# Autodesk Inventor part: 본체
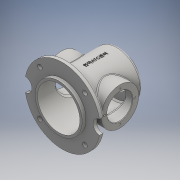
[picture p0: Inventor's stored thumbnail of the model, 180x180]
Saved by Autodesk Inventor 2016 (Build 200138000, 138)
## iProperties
Created: 2018-04
Part Number: 본체
Material: 일반
Document SubType Name: Modeling
Designer: 605-06
Density: 1 g/cm^3
Appearance: 기본값
Author: 605-06
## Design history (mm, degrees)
sketch "스케치1"
  geometry: C1 r 80 at (0, 0); 1 further point
  constraints: 1 centre point, 1 coincident
  dimensions: "d0" = 160 diameter of C1
extrude "돌출1" new body sketch "스케치1" distance "d1" = 10; taper "d2" = 0 deg
sketch "스케치2"
  geometry: C1 r 50 at (0, 0); 1 further point
  constraints: 1 centre point, 1 coincident
  dimensions: "d3" = 100 diameter of C1
extrude "돌출2" join sketch "스케치2" distance "d4" = 110; taper "d6" = 0 deg; dims "d5" = 18, "d7" = 0
sketch "스케치3"
  geometry: C1 r 40 at (0, 0); 1 further point
  constraints: 1 centre point, 1 coincident
  dimensions: "d8" = 80 diameter of C1
extrude "돌출3" join sketch "스케치3" distance "d9" = 5; taper "d10" = 0 deg
sketch "스케치4"
  geometry: C1 r 15 at (-80, 0); C2 r 15 at (80, 0); A1 r 80 centre (0, 0) between (-80, 0) and (80, 0) reference; 1 further point
  constraints: 2 centre point, 2 horizontal alignment, 2 point on circle
  dimensions: "d11" = 30 diameter of C1; "d12" = 30 diameter of C2
extrude "돌출4" cut sketch "스케치4" stored distance "d13" = 0; taper "d14" = 0 deg
sketch "스케치5"
  geometry: C1 r 40 at (60, 0); 1 further point
  constraints: 1 centre point, 1 horizontal alignment
  dimensions: "d15" = 80 diameter of C1; "d16" = 60 distance of C1.centre point (0, 0)
extrude "돌출5" join sketch "스케치5" stored distance "d17" = 124; taper "d18" = 0 deg
sketch "스케치6"
  geometry: C1 r 45 at (0, 0); 1 further point
  constraints: 1 centre point, 1 coincident
  dimensions: "d19" = 90 diameter of C1
extrude "돌출6" cut sketch "스케치6" distance "d20" = 120; taper "d21" = 0 deg
sketch "스케치7"
  geometry: C1 r 27 at (0, 0); 1 further point
  constraints: 1 centre point, 1 coincident
  dimensions: "d22" = 54 diameter of C1
extrude "돌출7" cut sketch "스케치7" stored distance "d23" = 120; taper "d24" = 0 deg
sketch "스케치8"
  geometry: C1 r 27 at (0, 0); C2 r 40 at (0, 0) reference; 1 further point
  constraints: 1 centre point, 1 concentric
  dimensions: "d25" = 54 diameter of C1
extrude "돌출8" cut sketch "스케치8" stored distance "d26" = 0; taper "d27" = 0 deg
sketch "스케치9"
  geometry: L1 (0, 67.5)-(0, -67.5); L2 (-47.73, 47.73)-(47.73, -47.73); L3 (-67.5, 0)-(67.5, 0); L4 (-47.73, -47.73)-(47.73, 47.73); L5 (0, -67.5)-(0, 67.5); L6 (47.73, -47.73)-(-47.73, 47.73); L7 (67.5, 0)-(-67.5, 0); L8 (47.73, 47.73)-(-47.73, -47.73); A1 r 67.5 centre (0, 0) between (0, 67.5) and (0, -67.5); 20 further points
  constraints: 16 end point, 9 midpoint, 5 coincident, 2 point on circle, 1 centre point, 1 vertical, 41 other
  dimensions: "d28" = 135 diameter of A1; "d31" = 360 deg dimension on A1.centre L1.start (derived)
hole "구멍1" sketch "스케치9" at (-47.73, 47.73), (47.73, 47.73), (47.73, -47.73), (-47.73, -47.73) diameter "d33" = 10; stored, may be unused: countersink angle "d37" = 90 deg, drill point angle "d39" = 118 deg; dims "d34" = 6, "d35" = 4, "d36" = 2, "d38" = 8
sketch "스케치10"
  geometry: C1 r 40 at (0, 0) reference; A1 r 32.5 centre (0, 0) between (0, 32.5) and (-32.5, 0); 3 further points
  constraints: 4 point on circle, 2 horizontal alignment, 2 vertical alignment, 1 centre point, 1 concentric
  dimensions: "d40" = 65 diameter of A1
hole "구멍2" sketch "스케치10" at (0, 32.5), (-32.5, 0), (0, -32.5), (32.5, 0) diameter "d41" = 3.459; stored, may be unused: countersink angle "d45" = 90 deg, drill point angle "d47" = 118 deg; dims "d42" = 8, "d43" = 4, "d44" = 2, "d46" = 10
sketch "스케치11"
  geometry: A1 r 32.5 centre (0, 0) between (32.5, 0) and (0, 32.5); 3 further points
  constraints: 4 point on circle, 2 horizontal alignment, 2 vertical alignment, 1 centre point, 1 coincident
  dimensions: "d48" = 65 diameter of A1
hole "구멍3" sketch "스케치11" at (0, 32.5), (-32.5, 0), (0, -32.5), (32.5, 0) diameter "d49" = 3.459; stored, may be unused: countersink angle "d53" = 90 deg, drill point angle "d55" = 118 deg; dims "d50" = 8, "d51" = 4, "d52" = 2, "d54" = 10
fillet "모깎기1" dims "d56" = 5
fillet "모깎기2" dims "d57" = 3
chamfer "모따기1" distance "d58" = 1; stored, may be unused: second distance "d59" = 2, angle "d60" = 45 deg
node "작업 평면1"
sketch "스케치12"
  geometry: L1 (9.52, 45.551)-(9.52, 95.326); L2 (9.52, 95.326)-(-10.221, 95.326); L3 (-10.221, 95.326)-(-10.221, 45.551); L4 (-10.221, 45.551)-(9.52, 45.551); L5 (0, 0)-(0, 70)
  constraints: 2 end point, 1 vertical, 2 other
  dimensions: "d62" = 70 distance of L5.start L5.end
feature "엠보싱1" sketch "스케치12" dims "d63" = 0.5, "d64" = 0
chamfer "모따기2" distance "d65" = 3; stored, may be unused: second distance "d66" = 2, angle "d67" = 45 deg
node "솔리드1"
mirror "대칭1"
other parameters: "d61" = 105.25
